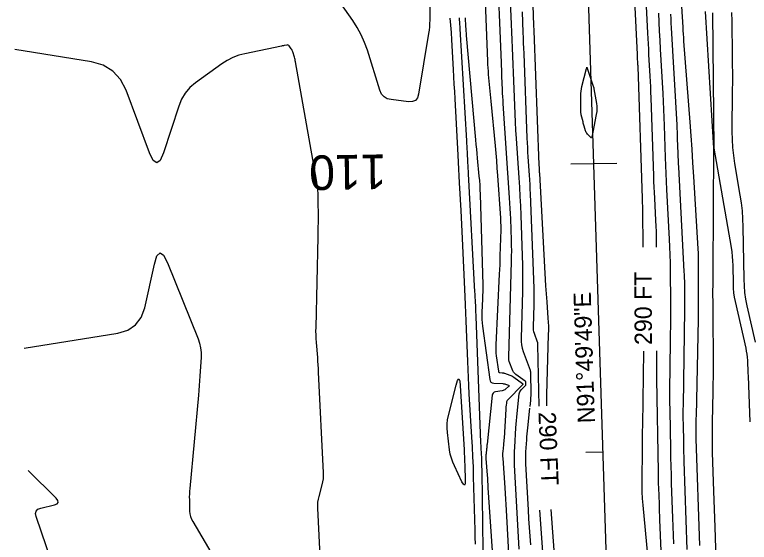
# Model space of a CAD drawing. Extents: x 1768942 to 1774819, y 723037 to 732099.
# Drawn here: x 1770607 to 1770861.8, y 725105.6 to 725288.6 of the extents above; entities that cross this region are included whole.
import ezdxf

# ---------------------------------------------------------------- set-up
doc = ezdxf.new("R2010")
doc.units = 0
for name, color, linetype in [('R_Contour Annot', 7, 'Continuous'), ('R_Contours', 7, 'Continuous'), ('R_Horz Alg', 7, 'Continuous'), ('R_Horz Alg Annot', 7, 'Continuous')]:
    doc.layers.add(name, color=color, linetype=linetype)

msp = doc.modelspace()

# ---------------------------------------------------------------- linework, layer by layer
at = {"layer": 'R_Contours'}
for points in [[(1770791.56, 725152.97), (1770791.57, 725154.53), (1770791.62, 725156.75), (1770792.2, 725177.75), (1770792.22, 725179.16), (1770792.21, 725180.56), (1770792.15, 725181.97), (1770792.06, 725183.37), (1770791.63, 725188.99), (1770791.52, 725190.4), (1770791.43, 725191.81), (1770791.34, 725193.21), (1770791.25, 725194.62), (1770789.09, 725233.56), (1770789.09, 725233.62), (1770789.09, 725233.67), (1770789.08, 725233.73), (1770789.08, 725233.79), (1770789.07, 725234.01), (1770789.06, 725234.06), (1770789.06, 725234.12), (1770789.06, 725234.17), (1770789.05, 725234.23), (1770788.98, 725235.53), (1770788.97, 725235.77), (1770788.96, 725236), (1770788.95, 725236.24), (1770788.94, 725236.47), (1770787.16, 725282.96), (1770787.15, 725283.13), (1770787.15, 725283.3), (1770787.14, 725283.47), (1770787.13, 725283.64), (1770787.11, 725284.31), (1770787.1, 725284.48), (1770787.09, 725284.65), (1770787.09, 725284.82), (1770787.08, 725284.99), (1770785.47, 725332.57)], [(1770750.99, 725291.35), (1770750.96, 725286.7), (1770750.93, 725285.54), (1770750.85, 725284.38), (1770750.73, 725283.23), (1770750.57, 725282.08), (1770747.12, 725261.03), (1770746.72, 725259.74), (1770746, 725258.87), (1770744.97, 725258.42), (1770743.62, 725258.39), (1770737.59, 725259.11), (1770736.22, 725259.45), (1770735.11, 725260.1), (1770734.26, 725261.07), (1770733.68, 725262.36), (1770729.36, 725276.23), (1770728.39, 725278.98), (1770727.22, 725281.62), (1770725.84, 725284.17), (1770724.26, 725286.61), (1770706.05, 725312.54)], [(1770821.07, 725312.28), (1770822.87, 725274.73), (1770822.89, 725274.39), (1770822.91, 725274.05), (1770822.93, 725273.71), (1770822.94, 725273.37), (1770823.02, 725272.01), (1770823.04, 725271.67), (1770823.06, 725271.33), (1770823.07, 725270.99), (1770823.08, 725270.65), (1770824.61, 725224.8), (1770824.62, 725224.45), (1770824.63, 725224.11), (1770824.65, 725223.77), (1770824.66, 725223.43), (1770824.74, 725222.06), (1770824.75, 725221.72), (1770824.77, 725221.38), (1770824.77, 725221.04), (1770824.78, 725220.7), (1770824.86, 725207.96)], [(1770829.63, 725207.99), (1770829.62, 725209.48), (1770829.6, 725211.41), (1770829.55, 725213.35), (1770829.49, 725215.28), (1770829.39, 725217.21), (1770828.98, 725224.94), (1770828.88, 725226.87), (1770828.79, 725228.8), (1770828.71, 725230.73), (1770828.64, 725232.66), (1770827.74, 725259.8), (1770827.68, 725261.67), (1770827.6, 725263.53), (1770827.51, 725265.39), (1770827.41, 725267.26), (1770826.99, 725274.71), (1770826.88, 725276.57), (1770826.79, 725278.43), (1770826.69, 725280.29), (1770826.6, 725282.16), (1770825.13, 725312.71)], [(1770769.58, 725307.9), (1770770.97, 725272.4), (1770771.02, 725271.25), (1770771.09, 725270.1), (1770771.17, 725268.94), (1770771.27, 725267.79), (1770771.68, 725263.19), (1770771.78, 725262.04), (1770771.89, 725260.89), (1770771.99, 725259.74), (1770772.11, 725258.59), (1770773.61, 725243.14), (1770773.85, 725240.56), (1770774.07, 725237.98), (1770774.28, 725235.4), (1770774.46, 725232.81), (1770775.46, 725217.97), (1770775.48, 725217.64), (1770775.5, 725217.31), (1770775.52, 725216.98), (1770775.53, 725216.64), (1770775.58, 725215.31), (1770775.59, 725214.98), (1770775.59, 725214.65), (1770775.59, 725214.32), (1770775.58, 725213.98), (1770775.32, 725205), (1770775.27, 725203.39), (1770775.21, 725201.79), (1770775.14, 725200.18), (1770775.07, 725198.57), (1770773.87, 725174.1), (1770773.84, 725173.14), (1770773.86, 725172.17), (1770773.93, 725171.22), (1770774.03, 725170.26), (1770774.76, 725164.93), (1770774.82, 725164.75), (1770774.91, 725164.61), (1770775.05, 725164.53), (1770775.24, 725164.49), (1770776.08, 725164.44), (1770776.29, 725164.42), (1770776.5, 725164.38), (1770776.7, 725164.33), (1770776.9, 725164.27), (1770778.72, 725163.65), (1770779.08, 725163.51), (1770779.43, 725163.34), (1770779.76, 725163.15), (1770780.08, 725162.93), (1770783.1, 725160.75), (1770783.14, 725160.71), (1770783.17, 725160.67), (1770783.18, 725160.63), (1770783.19, 725160.58), (1770783.2, 725160.37), (1770783.19, 725160.32), (1770783.18, 725160.28), (1770783.16, 725160.24), (1770783.13, 725160.2), (1770778.01, 725155.02), (1770777.83, 725154.82), (1770777.7, 725154.59), (1770777.61, 725154.34), (1770777.55, 725154.07), (1770777.43, 725152.95), (1770777.4, 725152.68), (1770777.38, 725152.4), (1770777.35, 725152.12), (1770777.34, 725151.84), (1770776.72, 725141.81), (1770776.68, 725141.23), (1770776.64, 725140.65), (1770776.59, 725140.07), (1770776.53, 725139.48), (1770776.29, 725137.15), (1770776.25, 725136.57), (1770776.23, 725135.99), (1770776.23, 725135.41), (1770776.26, 725134.82), (1770776.96, 725124.48), (1770777.08, 725122.56), (1770777.2, 725120.64), (1770777.32, 725118.72), (1770777.43, 725116.8), (1770778.94, 725089.19)], [(1770782, 725103.25), (1770780.4, 725132.46), (1770780.34, 725134), (1770780.32, 725135.54), (1770780.35, 725137.08), (1770780.42, 725138.61), (1770780.83, 725145.3), (1770780.91, 725146.57), (1770781.02, 725147.83), (1770781.13, 725149.09), (1770781.26, 725150.35), (1770782.01, 725157.11), (1770782.08, 725157.49), (1770782.21, 725157.85), (1770782.4, 725158.17), (1770782.66, 725158.47), (1770784.14, 725159.97), (1770784.23, 725160.08), (1770784.29, 725160.2), (1770784.33, 725160.34), (1770784.34, 725160.48), (1770784.32, 725161.07), (1770784.3, 725161.21), (1770784.25, 725161.33), (1770784.18, 725161.44), (1770784.07, 725161.54), (1770780.84, 725163.88), (1770780.41, 725164.24), (1770780.04, 725164.65), (1770779.75, 725165.11), (1770779.52, 725165.63), (1770778.73, 725167.77), (1770778.56, 725168.31), (1770778.44, 725168.86), (1770778.38, 725169.42), (1770778.37, 725169.98), (1770779.33, 725203.04), (1770779.37, 725204.88), (1770779.38, 725206.72), (1770779.36, 725208.56), (1770779.3, 725210.4), (1770779.03, 725217.76), (1770778.95, 725219.59), (1770778.86, 725221.43), (1770778.76, 725223.27), (1770778.64, 725225.11), (1770776.44, 725257.77), (1770776.37, 725258.95), (1770776.3, 725260.14), (1770776.24, 725261.32), (1770776.19, 725262.5), (1770776.01, 725267.24), (1770775.97, 725268.43), (1770775.92, 725269.61), (1770775.87, 725270.8), (1770775.83, 725271.98), (1770774.4, 725307.9)], [(1770778.79, 725296.12), (1770779.44, 725279.88), (1770779.55, 725277.03), (1770779.66, 725274.18), (1770779.77, 725271.32), (1770779.88, 725268.47), (1770780.32, 725257.05), (1770780.44, 725254.19), (1770780.58, 725251.34), (1770780.74, 725248.49), (1770780.92, 725245.64), (1770781.84, 725232.01), (1770782.04, 725228.78), (1770782.22, 725225.56), (1770782.38, 725222.33), (1770782.52, 725219.11), (1770783.05, 725204.97), (1770783.14, 725201.88), (1770783.17, 725198.78), (1770783.16, 725195.69), (1770783.1, 725192.59), (1770782.62, 725176.43), (1770782.64, 725175.24), (1770782.78, 725174.07), (1770783.02, 725172.91), (1770783.38, 725171.78), (1770785.74, 725165.36), (1770785.8, 725165.19), (1770785.84, 725165.02), (1770785.87, 725164.84), (1770785.88, 725164.66), (1770785.9, 725163.94), (1770785.91, 725163.76), (1770785.91, 725163.58), (1770785.92, 725163.4), (1770785.92, 725163.22), (1770786.03, 725158.33), (1770786.03, 725157.45), (1770786.01, 725156.58), (1770785.95, 725155.71), (1770785.87, 725154.83), (1770785.64, 725152.73)], [(1770844.61, 725104.55), (1770843.32, 725141.53), (1770843.31, 725141.6), (1770843.31, 725141.67), (1770843.31, 725141.74), (1770843.31, 725141.81), (1770843.3, 725142.1), (1770843.3, 725142.17), (1770843.3, 725142.24), (1770843.3, 725142.31), (1770843.3, 725142.38), (1770843.36, 725146.52), (1770843.38, 725147.24), (1770843.39, 725147.95), (1770843.4, 725148.67), (1770843.42, 725149.38), (1770844.15, 725182.98), (1770844.17, 725183.88), (1770844.18, 725184.77), (1770844.18, 725185.66), (1770844.18, 725186.56), (1770844.15, 725190.13), (1770844.15, 725191.02), (1770844.15, 725191.92), (1770844.15, 725192.81), (1770844.15, 725193.7), (1770844.21, 725201.21), (1770844.21, 725202.76), (1770844.18, 725204.31), (1770844.13, 725205.85), (1770844.05, 725207.4), (1770842.52, 725232.51), (1770842.23, 725237.21), (1770841.92, 725241.91), (1770841.59, 725246.61), (1770841.24, 725251.3), (1770839.12, 725279.43), (1770839.03, 725280.64), (1770838.95, 725281.86), (1770838.87, 725283.07), (1770838.8, 725284.28), (1770838.4, 725291.41)], [(1770782.97, 725289.57), (1770783.26, 725282.35), (1770783.33, 725280.54), (1770783.4, 725278.74), (1770783.47, 725276.93), (1770783.54, 725275.13), (1770784.67, 725245.76), (1770784.74, 725244.15), (1770784.82, 725242.55), (1770784.91, 725240.94), (1770785.01, 725239.33), (1770785.44, 725232.9), (1770785.54, 725231.29), (1770785.63, 725229.68), (1770785.71, 725228.08), (1770785.78, 725226.47), (1770787.01, 725193.76), (1770787.05, 725192.3), (1770787.07, 725190.85), (1770787.06, 725189.4), (1770787.03, 725187.94), (1770786.81, 725180.34), (1770786.82, 725179.78), (1770786.88, 725179.23), (1770787, 725178.69), (1770787.16, 725178.16), (1770788.27, 725175.14), (1770788.3, 725175.06), (1770788.32, 725174.98), (1770788.33, 725174.9), (1770788.34, 725174.81), (1770788.35, 725174.47), (1770788.35, 725174.39), (1770788.35, 725174.3), (1770788.36, 725174.22), (1770788.36, 725174.13), (1770788.81, 725152.86)], [(1770835.59, 725105.08), (1770835.48, 725108.08), (1770835.37, 725111.08), (1770835.26, 725114.08), (1770834.84, 725126.09), (1770834.74, 725129.09), (1770834.66, 725132.09), (1770834.58, 725135.09), (1770834.53, 725138.09), (1770834.3, 725151.29), (1770834.26, 725154.49), (1770834.24, 725157.69), (1770834.25, 725160.89), (1770834.28, 725164.09), (1770834.48, 725177.84), (1770834.52, 725180.59), (1770834.53, 725183.33), (1770834.54, 725186.08), (1770834.53, 725188.83), (1770834.46, 725199.82), (1770834.43, 725202.57), (1770834.36, 725205.31), (1770834.26, 725208.06), (1770834.13, 725210.8), (1770833.22, 725227.93), (1770833.07, 725230.71), (1770832.95, 725233.49), (1770832.83, 725236.27), (1770832.73, 725239.05), (1770832.36, 725250.17), (1770832.26, 725252.95), (1770832.15, 725255.74), (1770832.01, 725258.51), (1770831.86, 725261.29), (1770831, 725276.56), (1770830.83, 725279.69), (1770830.66, 725282.81), (1770830.5, 725285.94), (1770830.35, 725289.06)], [(1770834.44, 725288.8), (1770834.53, 725287.19), (1770834.61, 725285.59), (1770834.7, 725283.98), (1770836.6, 725250.38), (1770836.67, 725249.16), (1770836.72, 725247.94), (1770836.78, 725246.72), (1770836.82, 725245.5), (1770836.98, 725240.61), (1770837.03, 725239.39), (1770837.08, 725238.17), (1770837.13, 725236.95), (1770837.19, 725235.73), (1770839.13, 725199.49), (1770839.19, 725198.39), (1770839.23, 725197.28), (1770839.25, 725196.18), (1770839.27, 725195.07), (1770839.29, 725190.65), (1770839.3, 725189.55), (1770839.3, 725188.45), (1770839.29, 725187.34), (1770839.28, 725186.24), (1770838.79, 725153.23), (1770838.78, 725151.6), (1770838.77, 725149.96), (1770838.78, 725148.33), (1770838.8, 725146.69), (1770838.91, 725140.15), (1770838.95, 725138.52), (1770838.98, 725136.88), (1770839.03, 725135.25), (1770839.08, 725133.61), (1770840.15, 725103.11)], [(1770850.54, 725092.7), (1770849.89, 725110.9), (1770849.78, 725114.01), (1770849.67, 725117.13), (1770849.57, 725120.24), (1770849.47, 725123.36), (1770849.07, 725136.8), (1770849.01, 725139.43), (1770848.98, 725142.05), (1770848.98, 725144.68), (1770849.03, 725147.3), (1770849.26, 725157.81), (1770849.3, 725160.44), (1770849.33, 725163.06), (1770849.34, 725165.69), (1770849.33, 725168.32), (1770849.21, 725184.78), (1770849.19, 725188.4), (1770849.18, 725192.02), (1770849.19, 725195.64), (1770849.21, 725199.25), (1770849.53, 725242.24), (1770849.53, 725242.25), (1770846.61, 725289.63)], [(1770848.96, 725289.17), (1770849.53, 725242.25), (1770849.53, 725242.24), (1770855.45, 725207.87), (1770855.69, 725206.32), (1770855.86, 725204.75), (1770855.98, 725203.19), (1770856.03, 725201.61), (1770856.13, 725195.31), (1770856.19, 725193.74), (1770856.34, 725192.18), (1770856.56, 725190.63), (1770856.87, 725189.08), (1770860.52, 725172.97), (1770860.73, 725171.91), (1770860.9, 725170.85), (1770861.03, 725169.78), (1770861.1, 725168.7), (1770861.32, 725164.38), (1770861.37, 725163.3), (1770861.42, 725162.22), (1770861.47, 725161.14), (1770861.51, 725160.06), (1770861.99, 725147.39)], [(1770855.64, 725289.38), (1770855.71, 725286.38), (1770855.86, 725274.36), (1770855.89, 725271.35), (1770855.9, 725268.35), (1770855.9, 725265.34), (1770855.88, 725262.34), (1770855.75, 725248.08), (1770855.79, 725245.3), (1770855.95, 725242.53), (1770856.24, 725239.77), (1770856.65, 725237.02), (1770858.54, 725226.04), (1770858.96, 725223.29), (1770859.27, 725220.53), (1770859.47, 725217.76), (1770859.57, 725214.98), (1770859.84, 725196.92), (1770859.94, 725194.58), (1770860.16, 725192.26), (1770860.49, 725189.95), (1770860.95, 725187.66), (1770863.8, 725175.06)], [(1770766.83, 725104.95), (1770766.77, 725107.4), (1770766.71, 725109.84), (1770766.19, 725128.39), (1770766.08, 725131.83), (1770765.94, 725135.27), (1770765.78, 725138.71), (1770765.58, 725142.14), (1770764.68, 725157.15), (1770764.52, 725159.96), (1770764.38, 725162.76), (1770764.25, 725165.56), (1770764.13, 725168.37), (1770763.71, 725179.59), (1770763.6, 725182.39), (1770763.48, 725185.2), (1770763.36, 725188), (1770763.24, 725190.81), (1770762.31, 725211.02), (1770762.2, 725213.43), (1770762.08, 725215.83), (1770761.95, 725218.24), (1770761.82, 725220.64), (1770761.29, 725230.26), (1770761.16, 725232.67), (1770761.03, 725235.07), (1770760.9, 725237.48), (1770760.78, 725239.89), (1770759.76, 725259.38), (1770759.62, 725261.93), (1770759.48, 725264.49), (1770759.34, 725267.05), (1770759.19, 725269.6), (1770758.61, 725279.83), (1770758.45, 725282.38), (1770758.26, 725284.93), (1770758.05, 725287.34)], [(1770769.58, 725094.03), (1770769.11, 725130.03), (1770769.1, 725130.57), (1770769.09, 725131.11), (1770769.08, 725131.65), (1770769.06, 725132.18), (1770769, 725134.43), (1770768.98, 725134.92), (1770768.97, 725135.41), (1770768.94, 725135.9), (1770768.91, 725136.38), (1770768.8, 725138.33), (1770768.77, 725138.82), (1770768.74, 725139.31), (1770768.72, 725139.8), (1770768.7, 725140.28), (1770767.05, 725183.94), (1770767.02, 725184.65), (1770766.99, 725185.37), (1770766.96, 725186.08), (1770766.93, 725186.8), (1770766.8, 725189.66), (1770766.77, 725190.37), (1770766.73, 725191.09), (1770766.69, 725191.8), (1770766.65, 725192.52), (1770764.4, 725233.37), (1770764.35, 725234.33), (1770764.3, 725235.28), (1770764.25, 725236.24), (1770764.2, 725237.2), (1770764, 725241.02), (1770763.94, 725241.98), (1770763.89, 725242.93), (1770763.84, 725243.89), (1770763.79, 725244.84), (1770761.56, 725283.71), (1770761.51, 725284.47), (1770761.45, 725285.22), (1770761.39, 725285.98), (1770761.31, 725286.73), (1770761.24, 725287.46)], [(1770763.28, 725287.53), (1770763.4, 725284.48), (1770763.44, 725283.69), (1770763.48, 725282.9), (1770763.54, 725282.11), (1770763.61, 725281.33), (1770766.84, 725245.13), (1770766.98, 725243.56), (1770767.12, 725242), (1770767.27, 725240.43), (1770767.42, 725238.86), (1770768.03, 725232.6), (1770768.17, 725231.03), (1770768.28, 725229.46), (1770768.37, 725227.89), (1770768.43, 725226.32), (1770769.32, 725194.84), (1770769.34, 725193.65), (1770769.34, 725192.46), (1770769.31, 725191.27), (1770769.27, 725190.08), (1770769.03, 725185.31), (1770769, 725184.13), (1770769.03, 725182.94), (1770769.1, 725181.75), (1770769.24, 725180.57), (1770771.77, 725162.14), (1770771.91, 725161.61), (1770772.19, 725161.22), (1770772.6, 725160.97), (1770773.14, 725160.86), (1770776.26, 725160.67), (1770776.51, 725160.64), (1770776.76, 725160.6), (1770777.01, 725160.54), (1770777.26, 725160.47), (1770778.23, 725160.13), (1770778.42, 725160.04), (1770778.5, 725159.92), (1770778.47, 725159.79), (1770778.32, 725159.64), (1770777.22, 725158.74), (1770776.96, 725158.55), (1770776.68, 725158.4), (1770776.39, 725158.29), (1770776.08, 725158.21), (1770773.72, 725157.79), (1770773.28, 725157.65), (1770772.95, 725157.41), (1770772.73, 725157.06), (1770772.62, 725156.61), (1770770.84, 725139.7), (1770770.8, 725139.28), (1770770.76, 725138.86), (1770770.71, 725138.44), (1770770.67, 725138.02), (1770770.5, 725136.35), (1770770.47, 725135.93), (1770770.45, 725135.51), (1770770.45, 725135.09), (1770770.47, 725134.67), (1770770.86, 725128.93), (1770770.94, 725127.83), (1770771.01, 725126.74), (1770771.09, 725125.64), (1770771.16, 725124.54), (1770773.55, 725089.23)], [(1770714, 725079.55), (1770712.13, 725117.45), (1770712.12, 725118.5), (1770712.19, 725119.53), (1770712.34, 725120.56), (1770712.58, 725121.58), (1770713.7, 725125.63), (1770713.94, 725126.64), (1770714.09, 725127.67), (1770714.16, 725128.71), (1770714.15, 725129.75), (1770712.44, 725164.58), (1770712.37, 725165.88), (1770712.29, 725167.18), (1770712.2, 725168.47), (1770712.1, 725169.77), (1770711.67, 725174.96), (1770711.59, 725176.26), (1770711.53, 725177.55), (1770711.51, 725178.85), (1770711.52, 725180.15), (1770712.26, 725211.59), (1770712.3, 725213.22), (1770712.32, 725214.86), (1770712.33, 725216.49), (1770712.33, 725218.13), (1770712.3, 725224.67), (1770712.26, 725226.3), (1770712.15, 725227.93), (1770711.97, 725229.55), (1770711.72, 725231.16), (1770704.42, 725272.18), (1770704.34, 725272.6), (1770704.24, 725273), (1770704.14, 725273.41), (1770704.02, 725273.81), (1770703.45, 725275.65), (1770703.35, 725275.93), (1770703.23, 725276.19), (1770703.09, 725276.45), (1770702.93, 725276.7), (1770702.19, 725277.76), (1770702.04, 725277.93), (1770701.86, 725278.03), (1770701.66, 725278.08), (1770701.44, 725278.06), (1770700.5, 725277.87), (1770700.26, 725277.82), (1770700.03, 725277.78), (1770699.79, 725277.73), (1770699.56, 725277.68), (1770686.87, 725275.05), (1770684.72, 725274.49), (1770682.67, 725273.71), (1770680.71, 725272.72), (1770678.85, 725271.51), (1770669.76, 725264.94), (1770667.8, 725263.29), (1770666.17, 725261.4), (1770664.87, 725259.27), (1770663.9, 725256.9), (1770658.64, 725240.72), (1770657.48, 725238.07), (1770656.28, 725237.17), (1770655.04, 725238.02), (1770653.76, 725240.62), (1770645.66, 725262.36), (1770643.73, 725266.14), (1770641.09, 725269.04), (1770637.73, 725271.07), (1770633.65, 725272.22), (1770607.03, 725276.53)], [(1770610.37, 725172.94), (1770642.8, 725178.17), (1770646.25, 725179.18), (1770648.96, 725180.99), (1770650.91, 725183.59), (1770652.12, 725186.98), (1770655.47, 725202.13), (1770656.38, 725204.99), (1770657.45, 725206.01), (1770658.67, 725205.18), (1770660.04, 725202.51), (1770670.65, 725176.19), (1770671.17, 725174.65), (1770671.52, 725173.07), (1770671.68, 725171.47), (1770671.67, 725169.84), (1770671.24, 725163.25), (1770671.13, 725161.61), (1770671.01, 725159.96), (1770670.87, 725158.32), (1770670.73, 725156.68), (1770667.73, 725124.34), (1770667.65, 725123.36), (1770667.61, 725122.38), (1770667.59, 725121.39), (1770667.6, 725120.41), (1770667.7, 725116.47), (1770667.78, 725115.5), (1770667.99, 725114.57), (1770668.31, 725113.67), (1770668.75, 725112.81), (1770687.9, 725080.38)], [(1770825.04, 725171.96), (1770824.69, 725146.3), (1770824.66, 725143.98), (1770824.63, 725141.66), (1770824.6, 725139.34), (1770824.58, 725137.02), (1770824.47, 725127.74), (1770824.47, 725125.42), (1770824.54, 725123.11), (1770824.67, 725120.79), (1770824.86, 725118.48), (1770826.51, 725101.21)], [(1770832.2, 725078.55), (1770830.79, 725113.41), (1770830.73, 725114.8), (1770830.68, 725116.19), (1770830.63, 725117.57), (1770830.58, 725118.96), (1770830.39, 725124.52), (1770830.34, 725125.91), (1770830.3, 725127.3), (1770830.27, 725128.69), (1770830.24, 725130.08), (1770829.69, 725162.21), (1770829.67, 725163.81), (1770829.66, 725165.41), (1770829.66, 725167.01), (1770829.68, 725168.62), (1770829.73, 725171.99)], [(1770785.58, 725152.2), (1770784.83, 725145.33), (1770784.72, 725144.3), (1770784.62, 725143.27), (1770784.54, 725142.23), (1770784.47, 725141.2), (1770784.22, 725137.06), (1770784.17, 725136.02), (1770784.15, 725134.98), (1770784.16, 725133.95), (1770784.2, 725132.91), (1770785.09, 725116.86), (1770785.26, 725113.84), (1770785.45, 725110.82), (1770785.65, 725107.8), (1770785.86, 725104.78)], [(1770628.79, 725072.58), (1770614.45, 725114.59), (1770614.26, 725115.64), (1770614.45, 725116.47), (1770615.05, 725117.08), (1770616.04, 725117.47), (1770620.78, 725118.62), (1770621.71, 725118.98), (1770622.12, 725119.48), (1770622.03, 725120.13), (1770621.42, 725120.91), (1770611.66, 725130.59)], [(1770789.02, 725116.83), (1770791.16, 725087.79)], [(1770795.49, 725084.04), (1770793.05, 725117)]]:
    msp.add_lwpolyline(points, dxfattribs=at)
for points in [[(1770807.67, 725263.8), (1770807.75, 725263.5), (1770807.82, 725263.2), (1770807.88, 725262.89), (1770808.75, 725257.81), (1770808.87, 725256.86), (1770808.91, 725255.91), (1770808.85, 725254.96), (1770808.71, 725254.02), (1770807.51, 725247.84), (1770807.5, 725247.84), (1770807.5, 725247.84), (1770807.5, 725247.84), (1770807.5, 725247.84), (1770807.5, 725247.85), (1770807.49, 725247.85), (1770807.49, 725247.85), (1770807.49, 725247.85), (1770807.49, 725247.85), (1770807.16, 725246.19), (1770807.09, 725245.97), (1770806.99, 725245.87), (1770806.85, 725245.9), (1770806.67, 725246.05), (1770805.64, 725247.17), (1770805.42, 725247.44), (1770805.23, 725247.72), (1770805.08, 725248.03), (1770804.97, 725248.35), (1770804.52, 725249.9), (1770804.41, 725250.27), (1770804.31, 725250.64), (1770804.21, 725251.01), (1770804.12, 725251.39), (1770803.49, 725253.86), (1770803.45, 725254.05), (1770803.42, 725254.23), (1770803.4, 725254.42), (1770803.39, 725254.61), (1770803.39, 725255.37), (1770803.39, 725255.56), (1770803.38, 725255.75), (1770803.38, 725255.94), (1770803.38, 725256.13), (1770803.34, 725260.51), (1770803.35, 725261.3), (1770803.42, 725262.09), (1770803.55, 725262.87), (1770803.72, 725263.64), (1770805.36, 725269.87), (1770805.38, 725269.92), (1770805.39, 725269.98), (1770805.4, 725270.04), (1770805.41, 725270.09), (1770805.46, 725270.35), (1770805.47, 725270.38), (1770805.47, 725270.39), (1770805.48, 725270.39), (1770805.49, 725270.36), (1770805.53, 725270.2), (1770805.54, 725270.16), (1770805.55, 725270.12), (1770805.56, 725270.08), (1770805.58, 725270.05), (1770807.57, 725264.1)], [(1770762.93, 725136.5), (1770763, 725135.13), (1770763.05, 725133.77), (1770763.1, 725132.4), (1770763.25, 725126.94), (1770763.21, 725125.9), (1770763.01, 725125.51), (1770762.65, 725125.76), (1770762.14, 725126.67), (1770759.5, 725132.13), (1770758.92, 725133.47), (1770758.45, 725134.84), (1770758.1, 725136.24), (1770757.85, 725137.68), (1770757.08, 725143.71), (1770756.96, 725145.19), (1770756.98, 725146.67), (1770757.15, 725148.14), (1770757.45, 725149.6), (1770760.12, 725160.08), (1770760.63, 725161.75), (1770761.04, 725162.28), (1770761.34, 725161.68), (1770761.53, 725159.95), (1770762.86, 725137.86)]]:
    msp.add_lwpolyline(points, close=True, dxfattribs=at)
at = {"layer": 'R_Horz Alg'}
msp.add_line((1770821.12, 724822.68), (1770798.66, 725525.31), dxfattribs=at)
msp.add_line((1770821.12, 724822.68), (1770798.66, 725525.31), dxfattribs=at)
for points in [[(1770799.88, 725236.89), (1770815.88, 725237.14)], [(1770805.07, 725136.88), (1770811.07, 725137.07)]]:
    msp.add_lwpolyline(points, dxfattribs=at)

# ---------------------------------------------------------------- texts
at = {"layer": 'R_Contour Annot'}
for rotation, p in [(90.2862, (1770828.03, 725174.08)), (272.3724, (1770788.65, 725150.75))]:
    msp.add_text('290 FT', height=6, rotation=rotation, dxfattribs=at).set_placement(p)
at = {"layer": 'R_Horz Alg Annot'}
for s, height, rotation, p in [('110', 12, 180.8827, (1770735.83, 725240.15)), ('N91%%d49\'49"E', 6, 91.8304, (1770808.25, 725147.03))]:
    msp.add_text(s, height=height, rotation=rotation, dxfattribs=at).set_placement(p)

doc.saveas('drawing.dxf')
